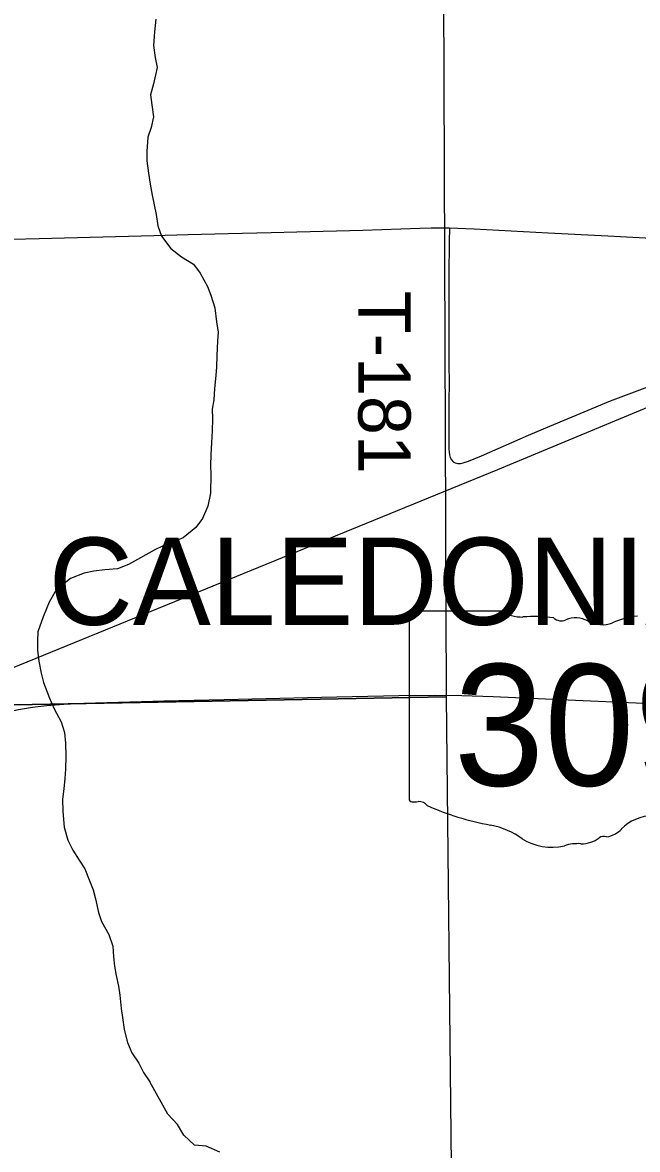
# Model space of a CAD drawing. Extents: x 0 to 45.9, y 0 to 22.
# Drawn here: x 4.006 to 4.674, y 18.26 to 19.483 of the extents above; entities that cross this region are included whole.
import ezdxf

# ---------------------------------------------------------------- set-up
doc = ezdxf.new("R2010")
doc.units = 0
for name, color, linetype in [('GM_X_Corporation_Text', 7, 'Continuous'), ('GM_X_County_Road', 7, 'Continuous'), ('GM_X_Minor_River', 7, 'Continuous'), ('GM_X_Rail_Line', 7, 'Continuous'), ('GM_X_Section', 7, 'Continuous'), ('GM_X_State_Location', 7, 'Continuous'), ('GM_X_State_Route', 7, 'Continuous'), ('GM_X_State_Shield', 7, 'Continuous'), ('GM_X_Township_Road', 7, 'Continuous'), ('GM_X_Township_Road_Text', 7, 'Continuous')]:
    doc.layers.add(name, color=color, linetype=linetype)

msp = doc.modelspace()

# ---------------------------------------------------------------- linework, layer by layer
at = {"layer": 'GM_X_County_Road'}
for points in [[(3.7417, 19.2433), (3.7665, 19.2437), (3.8473, 19.2447), (3.8753, 19.2452), (3.9343, 19.2462), (4.0244, 19.2484), (4.1486, 19.2514), (4.1859, 19.2525), (4.2294, 19.2538), (4.276, 19.2549), (4.3039, 19.2557), (4.3754, 19.2575), (4.4375, 19.2594), (4.4497, 19.2599), (4.4695, 19.2599)], [(4.4695, 19.2599), (4.4962, 19.2588), (4.5766, 19.2546), (4.6416, 19.2513), (4.6756, 19.2494), (4.7216, 19.2469), (4.7243, 19.2467), (4.7263, 19.2465)]]:
    msp.add_lwpolyline(points, dxfattribs=at)
at = {"layer": 'GM_X_Minor_River'}
for points in [[(4.151, 19.4865), (4.1496, 19.4724), (4.1485, 19.4577), (4.1502, 19.4447), (4.1522, 19.4337), (4.1484, 19.4163), (4.1451, 19.4042), (4.1464, 19.3935), (4.1484, 19.3802), (4.1459, 19.3688), (4.1423, 19.3583), (4.1412, 19.3427), (4.1413, 19.3325), (4.143, 19.3192), (4.1446, 19.3073), (4.147, 19.2955), (4.1511, 19.2742), (4.1531, 19.262), (4.157, 19.2509), (4.167, 19.2374), (4.1789, 19.2284), (4.1916, 19.2205), (4.199, 19.2105)], [(4.199, 19.2105), (4.207, 19.1963), (4.2106, 19.1867), (4.2148, 19.1729), (4.2168, 19.1577), (4.2185, 19.1467), (4.2179, 19.1372), (4.2172, 19.1209), (4.2169, 19.1091), (4.216, 19.0996), (4.2145, 19.0856), (4.2139, 19.0731), (4.2121, 19.0629), (4.2123, 19.0526), (4.212, 19.0397), (4.2114, 19.0264), (4.2107, 19.0139), (4.2101, 19.0021), (4.2107, 18.9926), (4.2102, 18.9718), (4.2073, 18.9578), (4.2017, 18.9446), (4.1943, 18.9345), (4.1804, 18.9234), (4.1694, 18.9187), (4.1594, 18.9151), (4.1491, 18.91), (4.1342, 18.9016), (4.1211, 18.8946), (4.1093, 18.8899), (4.0956, 18.8887), (4.0835, 18.8871), (4.0732, 18.885), (4.0583, 18.8792), (4.0429, 18.867), (4.0351, 18.8535), (4.0287, 18.8377), (4.023, 18.8215), (4.0225, 18.8116), (4.0226, 18.8014), (4.0239, 18.7896), (4.0263, 18.7766), (4.0291, 18.7663), (4.0355, 18.7494), (4.0406, 18.7379), (4.0482, 18.7237), (4.0518, 18.7123), (4.0527, 18.7005), (4.0531, 18.6864), (4.0528, 18.6724), (4.0522, 18.6621), (4.0509, 18.6511), (4.0495, 18.6398), (4.05, 18.6265), (4.0515, 18.6093), (4.0554, 18.5952), (4.0608, 18.5845), (4.0678, 18.5737), (4.074, 18.5641), (4.0787, 18.5522), (4.083, 18.5415), (4.0855, 18.5315), (4.0886, 18.517), (4.0921, 18.5071), (4.0998, 18.4929), (4.1041, 18.4803), (4.105, 18.4688), (4.1059, 18.4586), (4.1079, 18.4486), (4.1103, 18.4368), (4.1117, 18.4273), (4.1133, 18.4128), (4.1149, 18.4029), (4.1166, 18.39), (4.12, 18.3759), (4.1247, 18.3647), (4.1324, 18.3532), (4.1375, 18.3432), (4.1445, 18.3332)], [(4.2202, 18.2568), (4.2055, 18.2631), (4.193, 18.2644), (4.1814, 18.2752), (4.1743, 18.2867), (4.1639, 18.2978), (4.1445, 18.3332)]]:
    msp.add_lwpolyline(points, dxfattribs=at)
at = {"layer": 'GM_X_Rail_Line'}
msp.add_lwpolyline([(2.1, 18.0146), (2.1653, 18.0407), (2.5237, 18.1839), (2.7751, 18.2853), (3.1145, 18.4227), (3.3254, 18.5091), (3.739, 18.6778), (4.029, 18.7961), (4.522, 18.9975), (5.1108, 19.2426), (5.165, 19.2646), (5.2022, 19.2813), (5.2388, 19.2978), (5.2709, 19.314), (5.3278, 19.3464), (5.3593, 19.3662), (5.3837, 19.3819), (5.4121, 19.4026), (5.4579, 19.4381), (5.4785, 19.4538)], dxfattribs=at)
at = {"layer": 'GM_X_Section'}
for points in [[(3.494, 19.7024), (4.4624, 19.7057), (4.4658, 18.7509), (3.4889, 18.7329)], [(3.4889, 18.7329), (4.4658, 18.7509), (4.477, 17.7336), (3.4888, 17.7149)]]:
    msp.add_lwpolyline(points, close=True, dxfattribs=at)
at = {"layer": 'GM_X_State_Route'}
for points in [[(4.1477, 18.7462), (4.1597, 18.7465), (4.2249, 18.7479), (4.3306, 18.7505), (4.4145, 18.7523), (4.4549, 18.7527), (4.4829, 18.7525), (4.517, 18.7513), (4.6226, 18.7466), (4.6723, 18.7444), (4.7253, 18.742)], [(3.8097, 18.6644), (3.8106, 18.6648), (3.8387, 18.6782), (3.8697, 18.6925), (3.8954, 18.7037), (3.9212, 18.7142), (3.9358, 18.7195), (3.9535, 18.7252), (3.9685, 18.7294), (3.9865, 18.7339), (4.0017, 18.737), (4.017, 18.7395), (4.0324, 18.7414), (4.051, 18.7429), (4.0727, 18.7441), (4.1477, 18.7462)]]:
    msp.add_lwpolyline(points, dxfattribs=at)
at = {"layer": 'GM_X_State_Shield'}
for p, q in [((4.4258, 18.8405), (4.4258, 18.6403)), ((4.5256, 18.8439), (4.4291, 18.8439))]:
    msp.add_line(p, q, dxfattribs=at)
for centre, major_axis, start_param, end_param in [((4.4296, 18.8409), (0.00382, 0), 1.712693, 3.28349), ((4.5486, 18.8671), (0.037, 0), 4.042523, 4.731795), ((4.5608, 18.7316), (0.133, 0), 1.404758, 1.657858), ((4.591, 18.8419), (0.0107, 0), 3.836095, 5.185415), ((4.6067, 18.8188), (0.0222, 0), 0.950623, 2.079405), ((4.6826, 18.7828), (0.0703, 0), 1.699011, 2.107814), ((4.6354, 18.8505), (0.0267, 0), 4.081561, 5.145723), ((4.4296, 18.6399), (0.00385, 0), 3.00124, 4.508301), ((4.4302, 18.6604), (0.0294, 0), 4.665946, 4.897461), ((4.4362, 18.6288), (0.0106, 0), 0.519207, 1.627899), ((4.57, 18.8086), (0.2524, 0), 4.195997, 4.488961), ((4.6944, 18.5842), (0.0479, 0), 1.647645, 2.488434), ((4.4948, 18.5504), (0.079, 0), 0.823519, 1.323587), ((4.6338, 18.6209), (0.0282, 0), 4.937069, 5.64225), ((4.5802, 18.6278), (0.0501, 0), 4.026481, 4.996735), ((4.6092, 18.5586), (0.0412, 0), 1.495662, 1.94098), ((4.6128, 18.6128), (0.0267, 0), 4.691044, 5.507374), ((4.637, 18.5934), (0.00752, 0), 1.147584, 2.315152)]:
    msp.add_ellipse(centre, major_axis=major_axis, ratio=0.8, start_param=start_param, end_param=end_param, dxfattribs=at)
at = {"layer": 'GM_X_Township_Road'}
msp.add_lwpolyline([(4.4695, 19.2599), (4.4693, 19.2448), (4.469, 19.2086), (4.4688, 19.159), (4.4689, 19.1466), (4.4689, 19.1342), (4.4688, 19.1126), (4.4691, 19.0909), (4.469, 19.0723), (4.469, 19.0413), (4.469, 19.0196), (4.4692, 19.0166), (4.4696, 19.0136), (4.4703, 19.0108), (4.4716, 19.0082), (4.4734, 19.0061), (4.4758, 19.0047), (4.4786, 19.004), (4.4814, 19.0042), (4.4843, 19.0048), (4.4901, 19.0068), (4.5045, 19.0126), (4.5555, 19.035), (4.5784, 19.0445), (4.5985, 19.0528), (4.6156, 19.0601), (4.6442, 19.072), (4.6674, 19.0809), (4.6906, 19.0896)], dxfattribs=at)

# ---------------------------------------------------------------- texts
at = {"layer": 'GM_X_Corporation_Text'}
msp.add_text('CALEDONIA', height=0.0947, rotation=0, dxfattribs=at).set_placement((4.0346, 18.829))
at = {"layer": 'GM_X_State_Location'}
for s in ['s', 'r']:
    msp.add_text(s, height=0.000189, dxfattribs=at).set_placement((4.5869, 18.7271))
msp.add_text('309', height=0.000189, rotation=0, dxfattribs=at).set_placement((4.52, 18.7133))
at = {"layer": 'GM_X_State_Shield'}
msp.add_text('309', height=0.13184, dxfattribs=at).set_placement((4.4743, 18.6545))
at = {"layer": 'GM_X_Township_Road_Text'}
msp.add_text('T-181', height=0.05682, rotation=270, dxfattribs=at).set_placement((4.3706, 19.1914))

doc.saveas('drawing.dxf')
